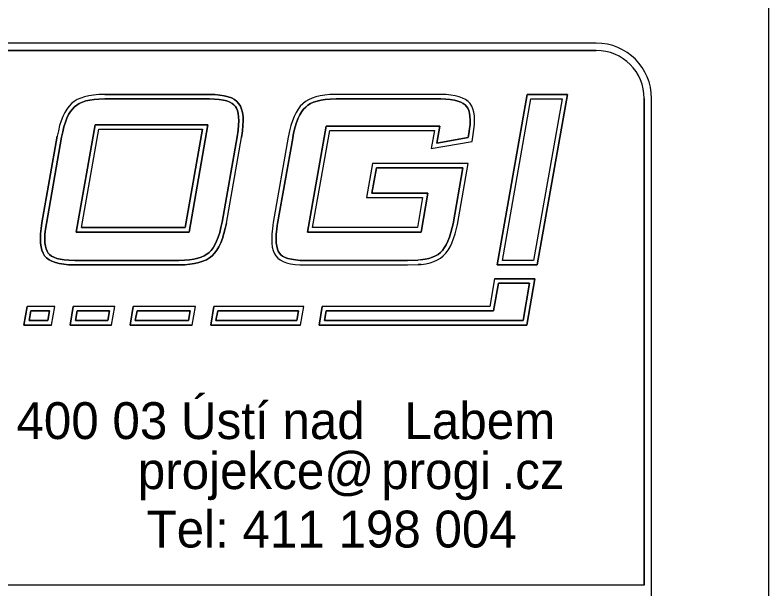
# Model space of a CAD drawing. Extents: x 249 to 564, y 49 to 194.
# Drawn here: x 544.18 to 563.59, y 70.96 to 85.75 of the extents above; entities that cross this region are included whole.
import ezdxf

# ---------------------------------------------------------------- set-up
doc = ezdxf.new("R2010")
doc.units = 0
doc.layers.add('000_rozpiska', color=7, linetype='Continuous')

msp = doc.modelspace()

# ---------------------------------------------------------------- linework, layer by layer
at = {"layer": '000_rozpiska'}
for p, q in [((563.594, 49.166), (563.594, 193.666)), ((559.147, 85.024), (472.697, 85.024)), ((559.147, 85.024), (472.697, 85.024)), ((559.147, 84.834), (532.072, 84.834)), ((552.155, 83.684), (552.037, 83.666)), ((552.288, 83.696), (552.155, 83.684)), ((552.447, 83.699), (552.288, 83.696)), ((555.144, 83.699), (552.447, 83.699)), ((555.278, 83.696), (555.144, 83.699)), ((555.402, 83.685), (555.278, 83.696)), ((555.515, 83.667), (555.402, 83.685)), ((556.592, 79.309), (557.366, 83.699)), ((557.366, 83.699), (558.402, 83.699)), ((558.402, 83.699), (557.629, 79.309)), ((545.832, 83.467), (545.911, 83.503)), ((545.911, 83.503), (546.001, 83.533)), ((546.001, 83.533), (546.102, 83.556)), ((546.102, 83.556), (546.214, 83.574)), ((546.214, 83.574), (546.338, 83.584)), ((546.338, 83.584), (546.493, 83.588)), ((546.493, 83.588), (549.183, 83.588)), ((549.183, 83.588), (549.316, 83.584)), ((549.316, 83.584), (549.436, 83.574)), ((549.436, 83.574), (549.543, 83.557)), ((549.543, 83.557), (549.633, 83.533)), ((549.633, 83.533), (549.706, 83.506)), ((549.706, 83.506), (549.77, 83.472)), ((551.656, 83.518), (551.587, 83.463)), ((551.735, 83.566), (551.656, 83.518)), ((551.826, 83.607), (551.735, 83.566)), ((551.867, 83.501), (551.788, 83.464)), ((551.926, 83.64), (551.826, 83.607)), ((551.957, 83.53), (551.867, 83.501)), ((552.037, 83.666), (551.926, 83.64)), ((552.059, 83.554), (551.957, 83.53)), ((552.169, 83.571), (552.059, 83.554)), ((552.294, 83.582), (552.169, 83.571)), ((552.449, 83.585), (552.294, 83.582)), ((555.142, 83.585), (552.449, 83.585)), ((555.272, 83.582), (555.142, 83.585)), ((555.388, 83.572), (555.272, 83.582)), ((555.492, 83.555), (555.388, 83.572)), ((555.586, 83.532), (555.492, 83.555)), ((555.62, 83.641), (555.515, 83.667)), ((555.66, 83.504), (555.586, 83.532)), ((555.706, 83.608), (555.62, 83.641)), ((555.722, 83.472), (555.66, 83.504)), ((555.782, 83.568), (555.706, 83.608)), ((555.847, 83.521), (555.782, 83.568)), ((555.899, 83.465), (555.847, 83.521)), ((556.728, 79.423), (557.461, 83.585)), ((557.461, 83.585), (558.267, 83.585)), ((558.267, 83.585), (557.533, 79.423)), ((560.382, 71.058), (560.382, 83.599)), ((560.572, 53.613), (560.572, 83.599)), ((560.572, 53.613), (560.572, 83.599)), ((545.605, 83.26), (545.655, 83.326)), ((545.655, 83.326), (545.707, 83.381)), ((545.707, 83.381), (545.766, 83.427)), ((545.766, 83.427), (545.832, 83.467)), ((549.77, 83.472), (549.815, 83.436)), ((549.815, 83.436), (549.853, 83.395)), ((549.853, 83.395), (549.882, 83.347)), ((549.882, 83.347), (549.905, 83.288)), ((551.468, 83.322), (551.415, 83.234)), ((551.524, 83.397), (551.468, 83.322)), ((551.587, 83.463), (551.524, 83.397)), ((551.611, 83.323), (551.562, 83.258)), ((551.664, 83.378), (551.611, 83.323)), ((551.721, 83.424), (551.664, 83.378)), ((551.788, 83.464), (551.721, 83.424)), ((555.77, 83.436), (555.722, 83.472)), ((555.808, 83.395), (555.77, 83.436)), ((555.837, 83.35), (555.808, 83.395)), ((555.862, 83.291), (555.837, 83.35)), ((555.881, 83.223), (555.862, 83.291)), ((555.938, 83.403), (555.899, 83.465)), ((555.97, 83.328), (555.938, 83.403)), ((555.993, 83.246), (555.97, 83.328)), ((545.514, 83.09), (545.558, 83.181)), ((545.558, 83.181), (545.605, 83.26)), ((549.905, 83.288), (549.924, 83.212)), ((549.924, 83.212), (549.935, 83.126)), ((549.935, 83.126), (549.939, 83.023)), ((551.366, 83.133), (551.322, 83.02)), ((551.415, 83.234), (551.366, 83.133)), ((551.515, 83.18), (551.47, 83.087)), ((551.562, 83.258), (551.515, 83.18)), ((555.893, 83.139), (555.881, 83.223)), ((555.899, 83.039), (555.893, 83.139)), ((556.007, 83.15), (555.993, 83.246)), ((556.013, 83.041), (556.007, 83.15)), ((545.437, 82.869), (545.474, 82.986)), ((545.474, 82.986), (545.514, 83.09)), ((545.751, 80.156), (546.238, 82.921)), ((546.238, 82.921), (549.146, 82.921)), ((548.659, 80.156), (549.146, 82.921)), ((549.935, 82.911), (549.922, 82.78)), ((549.939, 83.023), (549.935, 82.911)), ((551.285, 82.901), (551.249, 82.76)), ((551.322, 83.02), (551.285, 82.901)), ((551.43, 82.983), (551.395, 82.87)), ((551.47, 83.087), (551.43, 82.983)), ((555.884, 82.812), (555.896, 82.931)), ((555.896, 82.931), (555.899, 83.039)), ((555.998, 82.798), (556.01, 82.924)), ((556.01, 82.924), (556.013, 83.041)), ((545.376, 82.601), (545.405, 82.741)), ((545.405, 82.741), (545.437, 82.869)), ((545.887, 80.27), (546.334, 82.807)), ((546.334, 82.807), (549.01, 82.807)), ((548.563, 80.27), (549.01, 82.807)), ((549.922, 82.78), (549.897, 82.611)), ((551.249, 82.76), (551.232, 82.678)), ((551.36, 82.735), (551.344, 82.655)), ((551.395, 82.87), (551.36, 82.735)), ((551.707, 80.156), (552.188, 82.884)), ((551.843, 80.27), (552.283, 82.77)), ((552.188, 82.884), (555.116, 82.884)), ((552.283, 82.77), (554.98, 82.77)), ((554.98, 82.77), (554.898, 82.306)), ((555.116, 82.884), (555.039, 82.447)), ((555.866, 82.689), (555.884, 82.812)), ((555.979, 82.671), (555.998, 82.798)), ((544.872, 80.397), (545.265, 82.624)), ((544.985, 80.379), (545.376, 82.601)), ((549.897, 82.611), (549.509, 80.408)), ((549.621, 80.389), (550.009, 82.594)), ((551.216, 82.6), (550.828, 80.399)), ((551.328, 82.578), (550.941, 80.381)), ((551.232, 82.678), (551.216, 82.6)), ((551.344, 82.655), (551.328, 82.578)), ((555.039, 82.447), (555.849, 82.591)), ((555.849, 82.591), (555.866, 82.689)), ((555.947, 82.493), (555.979, 82.671)), ((554.898, 82.306), (555.947, 82.493)), ((553.388, 81.925), (553.233, 81.043)), ((553.484, 81.811), (553.369, 81.157)), ((555.847, 81.925), (553.388, 81.925)), ((555.712, 81.811), (553.484, 81.811)), ((555.458, 80.37), (555.712, 81.811)), ((555.569, 80.347), (555.847, 81.925)), ((553.369, 81.157), (554.812, 81.157)), ((554.812, 81.157), (554.635, 80.156)), ((553.233, 81.043), (554.676, 81.043)), ((554.676, 81.043), (554.54, 80.27)), ((544.962, 80.233), (544.985, 80.379)), ((549.509, 80.413), (549.479, 80.271)), ((550.828, 80.399), (550.82, 80.338)), ((550.941, 80.381), (550.933, 80.322)), ((544.949, 80.101), (544.962, 80.233)), ((545.887, 80.27), (548.563, 80.27)), ((549.479, 80.271), (549.449, 80.149)), ((550.806, 80.243), (550.792, 80.108)), ((550.82, 80.338), (550.806, 80.243)), ((550.92, 80.229), (550.906, 80.1)), ((550.933, 80.322), (550.92, 80.229)), ((554.54, 80.27), (551.843, 80.27)), ((555.402, 80.141), (555.435, 80.273)), ((555.435, 80.273), (555.458, 80.37)), ((555.512, 80.11), (555.546, 80.246)), ((555.546, 80.246), (555.569, 80.347)), ((544.944, 79.986), (544.949, 80.101)), ((545.751, 80.156), (548.659, 80.156)), ((549.41, 80.026), (549.37, 79.921)), ((549.449, 80.149), (549.41, 80.026)), ((550.792, 80.108), (550.788, 79.986)), ((550.906, 80.1), (550.902, 79.986)), ((554.635, 80.156), (551.707, 80.156)), ((555.325, 79.918), (555.366, 80.024)), ((555.366, 80.024), (555.402, 80.141)), ((555.473, 79.987), (555.512, 80.11)), ((544.948, 79.883), (544.944, 79.986)), ((544.96, 79.795), (544.948, 79.883)), ((544.978, 79.721), (544.96, 79.795)), ((549.325, 79.829), (549.279, 79.751)), ((549.37, 79.921), (549.325, 79.829)), ((550.788, 79.986), (550.791, 79.872)), ((550.791, 79.872), (550.804, 79.771)), ((550.902, 79.986), (550.905, 79.881)), ((550.905, 79.881), (550.916, 79.792)), ((555.234, 79.749), (555.28, 79.826)), ((555.28, 79.826), (555.325, 79.918)), ((555.381, 79.772), (555.43, 79.873)), ((555.43, 79.873), (555.473, 79.987)), ((545.002, 79.661), (544.978, 79.721)), ((545.031, 79.614), (545.002, 79.661)), ((545.066, 79.575), (545.031, 79.614)), ((549.176, 79.63), (549.119, 79.585)), ((549.229, 79.685), (549.176, 79.63)), ((549.279, 79.751), (549.229, 79.685)), ((550.804, 79.771), (550.826, 79.682)), ((550.826, 79.682), (550.855, 79.609)), ((550.855, 79.609), (550.895, 79.544)), ((550.916, 79.792), (550.935, 79.717)), ((550.935, 79.717), (550.958, 79.66)), ((550.958, 79.66), (550.987, 79.612)), ((550.987, 79.612), (551.023, 79.572)), ((555.074, 79.582), (555.132, 79.628)), ((555.132, 79.628), (555.185, 79.684)), ((555.185, 79.684), (555.234, 79.749)), ((555.208, 79.543), (555.273, 79.61)), ((555.273, 79.61), (555.329, 79.686)), ((555.329, 79.686), (555.381, 79.772)), ((545.114, 79.539), (545.066, 79.575)), ((545.174, 79.507), (545.114, 79.539)), ((545.25, 79.479), (545.174, 79.507)), ((545.341, 79.456), (545.25, 79.479)), ((545.446, 79.439), (545.341, 79.456)), ((545.564, 79.429), (545.446, 79.439)), ((545.721, 79.425), (545.564, 79.429)), ((548.393, 79.425), (545.721, 79.425)), ((548.546, 79.429), (548.393, 79.425)), ((548.669, 79.439), (548.546, 79.429)), ((548.782, 79.457), (548.669, 79.439)), ((548.883, 79.481), (548.782, 79.457)), ((548.973, 79.51), (548.883, 79.481)), ((549.053, 79.546), (548.973, 79.51)), ((549.119, 79.585), (549.053, 79.546)), ((550.895, 79.544), (550.946, 79.487)), ((550.946, 79.487), (551.009, 79.441)), ((551.009, 79.441), (551.086, 79.4)), ((551.023, 79.572), (551.07, 79.538)), ((551.07, 79.538), (551.133, 79.504)), ((551.133, 79.504), (551.207, 79.476)), ((551.207, 79.476), (551.297, 79.454)), ((551.297, 79.454), (551.403, 79.437)), ((551.403, 79.437), (551.522, 79.427)), ((551.522, 79.427), (551.675, 79.423)), ((551.675, 79.423), (554.283, 79.423)), ((554.283, 79.423), (554.557, 79.432)), ((554.624, 79.437), (554.557, 79.432)), ((554.624, 79.437), (554.737, 79.454)), ((554.737, 79.454), (554.836, 79.477)), ((554.836, 79.477), (554.926, 79.507)), ((554.926, 79.507), (555.004, 79.541)), ((554.967, 79.401), (555.056, 79.439)), ((555.004, 79.541), (555.074, 79.582)), ((555.056, 79.439), (555.138, 79.488)), ((555.138, 79.488), (555.208, 79.543)), ((557.533, 79.423), (556.728, 79.423)), ((551.086, 79.4), (551.173, 79.367)), ((551.173, 79.367), (551.275, 79.342)), ((551.275, 79.342), (551.389, 79.324)), ((551.389, 79.324), (551.516, 79.313)), ((551.516, 79.313), (551.674, 79.309)), ((551.674, 79.309), (554.284, 79.309)), ((554.284, 79.309), (554.564, 79.318)), ((554.637, 79.324), (554.564, 79.318)), ((554.637, 79.324), (554.758, 79.342)), ((554.758, 79.342), (554.867, 79.367)), ((554.867, 79.367), (554.967, 79.401)), ((557.629, 79.309), (556.592, 79.309)), ((556.529, 78.953), (556.403, 78.237)), ((556.625, 78.839), (556.499, 78.123)), ((556.529, 78.953), (557.566, 78.953)), ((556.625, 78.839), (557.43, 78.839)), ((557.43, 78.839), (557.261, 77.876)), ((557.566, 78.953), (557.356, 77.762)), ((544.408, 77.762), (544.492, 78.237)), ((545.204, 78.237), (544.492, 78.237)), ((544.544, 77.876), (544.587, 78.123)), ((545.068, 78.123), (544.587, 78.123)), ((545.025, 77.876), (545.068, 78.123)), ((545.121, 77.762), (545.204, 78.237)), ((545.596, 77.762), (545.679, 78.237)), ((546.748, 78.237), (545.679, 78.237)), ((545.731, 77.876), (545.775, 78.123)), ((546.612, 78.123), (545.775, 78.123)), ((546.569, 77.876), (546.612, 78.123)), ((546.664, 77.762), (546.748, 78.237)), ((547.139, 77.762), (547.223, 78.237)), ((548.826, 78.237), (547.223, 78.237)), ((547.275, 77.876), (547.319, 78.123)), ((548.69, 78.123), (547.319, 78.123)), ((548.647, 77.876), (548.69, 78.123)), ((548.742, 77.762), (548.826, 78.237)), ((549.217, 77.762), (549.301, 78.237)), ((551.617, 78.237), (549.301, 78.237)), ((549.353, 77.876), (549.397, 78.123)), ((551.481, 78.123), (549.397, 78.123)), ((551.437, 77.876), (551.481, 78.123)), ((551.533, 77.762), (551.617, 78.237)), ((552.008, 77.762), (552.092, 78.237)), ((556.403, 78.237), (552.092, 78.237)), ((552.144, 77.876), (552.187, 78.123)), ((556.499, 78.123), (552.187, 78.123)), ((545.025, 77.876), (544.544, 77.876)), ((546.569, 77.876), (545.731, 77.876)), ((548.647, 77.876), (547.275, 77.876)), ((551.437, 77.876), (549.353, 77.876)), ((557.261, 77.876), (552.144, 77.876)), ((545.121, 77.762), (544.408, 77.762)), ((546.664, 77.762), (545.596, 77.762)), ((548.742, 77.762), (547.139, 77.762)), ((551.533, 77.762), (549.217, 77.762)), ((557.356, 77.762), (552.008, 77.762)), ((560.382, 71.058), (532.072, 71.058))]:
    msp.add_line(p, q, dxfattribs=at)
for points in [[(532.072, 71.058), (532.072, 84.834), (559.147, 84.834)], [(549.566, 83.668), (549.45, 83.687), (549.323, 83.698), (549.186, 83.702), (546.491, 83.702), (546.332, 83.698), (546.201, 83.687), (546.08, 83.668), (545.97, 83.643), (545.869, 83.609), (545.779, 83.568), (545.701, 83.521), (545.63, 83.465), (545.568, 83.399), (545.511, 83.324), (545.457, 83.235), (545.41, 83.136), (545.366, 83.024), (545.327, 82.9), (545.294, 82.766), (545.265, 82.624), (544.872, 80.397), (544.849, 80.247), (544.836, 80.109), (544.83, 79.986), (544.834, 79.874), (544.847, 79.774), (544.869, 79.686), (544.899, 79.609), (544.939, 79.545), (544.989, 79.49), (545.053, 79.443), (545.127, 79.403), (545.216, 79.37), (545.317, 79.344), (545.432, 79.326), (545.558, 79.315), (545.718, 79.311), (548.395, 79.311), (548.552, 79.315), (548.683, 79.326), (548.803, 79.345), (548.914, 79.371), (549.014, 79.403), (549.105, 79.444), (549.184, 79.491), (549.253, 79.545), (549.316, 79.611), (549.373, 79.687), (549.426, 79.774), (549.474, 79.875), (549.518, 79.988), (549.559, 80.118), (549.59, 80.246), (549.621, 80.389), (550.009, 82.594), (550.035, 82.766), (550.048, 82.903), (550.053, 83.023), (550.049, 83.136), (550.036, 83.233), (550.014, 83.323), (549.984, 83.398), (549.944, 83.463), (549.894, 83.52), (549.832, 83.568), (549.754, 83.61), (549.667, 83.642), (549.566, 83.668)], [(546.491, 83.702), (546.332, 83.698), (546.201, 83.687), (546.08, 83.668), (545.97, 83.643), (545.869, 83.609), (545.779, 83.568), (545.701, 83.521), (545.63, 83.465), (545.568, 83.399), (545.511, 83.324), (545.457, 83.235), (545.41, 83.136), (545.366, 83.024), (545.327, 82.9), (545.294, 82.766), (545.265, 82.624)], [(546.491, 83.702), (549.186, 83.702), (549.323, 83.698), (549.45, 83.687), (549.566, 83.668), (549.667, 83.642), (549.754, 83.61), (549.832, 83.568), (549.894, 83.52), (549.944, 83.463), (549.984, 83.398), (550.014, 83.323), (550.036, 83.233), (550.049, 83.136), (550.053, 83.023), (550.048, 82.903), (550.035, 82.766), (550.009, 82.594)], [(555.62, 83.641), (555.515, 83.667), (555.402, 83.685), (555.278, 83.696), (555.144, 83.699), (552.447, 83.699), (552.288, 83.696), (552.155, 83.684), (552.037, 83.666), (551.926, 83.64), (551.826, 83.607), (551.735, 83.566), (551.656, 83.518), (551.587, 83.463), (551.524, 83.397), (551.468, 83.322), (551.415, 83.234), (551.366, 83.133), (551.322, 83.02), (551.285, 82.901), (551.249, 82.76), (551.232, 82.678), (551.216, 82.6), (550.828, 80.399), (550.82, 80.338), (550.806, 80.243), (550.792, 80.108), (550.788, 79.986), (550.791, 79.872), (550.804, 79.771), (550.826, 79.682), (550.855, 79.609), (550.895, 79.544), (550.946, 79.487), (551.009, 79.441), (551.086, 79.4), (551.173, 79.367), (551.275, 79.342), (551.389, 79.324), (551.516, 79.313), (551.674, 79.309), (554.284, 79.309), (554.564, 79.318), (554.637, 79.324), (554.758, 79.342), (554.867, 79.367), (554.967, 79.401), (555.056, 79.439), (555.138, 79.488), (555.208, 79.543), (555.273, 79.61), (555.329, 79.686), (555.381, 79.772), (555.43, 79.873), (555.473, 79.987), (555.512, 80.11), (555.546, 80.246), (555.569, 80.347), (555.847, 81.925), (553.388, 81.925), (553.233, 81.043), (554.676, 81.043), (554.54, 80.27), (551.843, 80.27), (552.283, 82.77), (554.98, 82.77), (554.898, 82.306), (555.947, 82.493), (555.979, 82.671), (555.998, 82.798), (556.01, 82.924), (556.013, 83.041), (556.007, 83.15), (555.993, 83.246), (555.97, 83.328), (555.938, 83.403), (555.899, 83.465), (555.847, 83.521), (555.782, 83.568), (555.706, 83.608), (555.62, 83.641)], [(558.402, 83.699), (557.366, 83.699), (556.592, 79.309), (557.629, 79.309), (558.402, 83.699)], [(560.382, 83.599), (560.382, 71.058), (532.072, 71.058)], [(549.939, 83.023), (549.935, 83.126), (549.924, 83.212), (549.905, 83.288), (549.882, 83.347), (549.853, 83.395), (549.815, 83.436), (549.77, 83.472), (549.706, 83.506), (549.633, 83.533), (549.543, 83.557), (549.436, 83.574), (549.316, 83.584), (549.183, 83.588), (546.493, 83.588), (546.338, 83.584), (546.214, 83.574), (546.102, 83.556), (546.001, 83.533), (545.911, 83.503), (545.832, 83.467), (545.766, 83.427), (545.707, 83.381), (545.655, 83.326), (545.605, 83.26), (545.558, 83.181), (545.514, 83.09), (545.474, 82.986), (545.437, 82.869), (545.405, 82.741), (545.376, 82.601), (544.985, 80.379), (544.962, 80.233), (544.949, 80.101), (544.944, 79.986), (544.948, 79.883), (544.96, 79.795), (544.978, 79.721), (545.002, 79.661), (545.031, 79.614), (545.066, 79.575), (545.114, 79.539), (545.174, 79.507), (545.25, 79.479), (545.341, 79.456), (545.446, 79.439), (545.564, 79.429), (545.721, 79.425), (548.393, 79.425), (548.546, 79.429), (548.669, 79.439), (548.782, 79.457), (548.883, 79.481), (548.973, 79.51), (549.053, 79.546), (549.119, 79.585), (549.176, 79.63), (549.229, 79.685), (549.279, 79.751), (549.325, 79.829), (549.37, 79.921), (549.41, 80.026), (549.449, 80.149), (549.479, 80.271), (549.509, 80.411), (549.897, 82.611), (549.922, 82.78), (549.935, 82.911), (549.939, 83.023)], [(549.183, 83.588), (549.316, 83.584), (549.436, 83.574), (549.543, 83.557), (549.633, 83.533), (549.706, 83.506), (549.77, 83.472), (549.815, 83.436), (549.853, 83.395), (549.882, 83.347), (549.905, 83.288), (549.924, 83.212), (549.935, 83.126), (549.939, 83.023), (549.935, 82.911), (549.922, 82.78), (549.897, 82.611), (549.509, 80.411), (549.479, 80.271), (549.449, 80.149), (549.41, 80.026), (549.37, 79.921), (549.325, 79.829), (549.279, 79.751), (549.229, 79.685), (549.176, 79.63), (549.119, 79.585), (549.053, 79.546), (548.973, 79.51), (548.883, 79.481), (548.782, 79.457), (548.669, 79.439), (548.546, 79.429), (548.393, 79.425), (545.721, 79.425), (545.564, 79.429), (545.446, 79.439), (545.341, 79.456), (545.25, 79.479), (545.174, 79.507), (545.114, 79.539), (545.066, 79.575), (545.031, 79.614), (545.002, 79.661), (544.978, 79.721), (544.96, 79.795), (544.948, 79.883), (544.944, 79.986), (544.949, 80.101), (544.962, 80.233), (544.985, 80.379), (545.376, 82.601), (545.405, 82.741), (545.437, 82.869), (545.474, 82.986), (545.514, 83.09), (545.558, 83.181), (545.605, 83.26), (545.655, 83.326), (545.707, 83.381), (545.766, 83.427), (545.832, 83.467), (545.911, 83.503), (546.001, 83.533), (546.102, 83.556), (546.214, 83.574), (546.338, 83.584), (546.493, 83.588), (549.183, 83.588)], [(555.142, 83.585), (555.272, 83.582), (555.388, 83.572), (555.492, 83.555), (555.586, 83.532), (555.66, 83.504), (555.722, 83.472), (555.77, 83.436), (555.808, 83.395), (555.837, 83.35), (555.862, 83.291), (555.881, 83.223), (555.893, 83.139), (555.899, 83.039), (555.896, 82.931), (555.884, 82.812), (555.866, 82.689), (555.849, 82.591), (555.039, 82.447), (555.116, 82.884), (552.188, 82.884), (551.707, 80.156), (554.635, 80.156), (554.812, 81.157), (553.369, 81.157), (553.484, 81.811), (555.712, 81.811), (555.458, 80.37), (555.435, 80.273), (555.402, 80.141), (555.366, 80.024), (555.325, 79.918), (555.28, 79.826), (555.234, 79.749), (555.185, 79.684), (555.132, 79.628), (555.074, 79.582), (555.004, 79.541), (554.926, 79.507), (554.836, 79.477), (554.737, 79.454), (554.624, 79.437), (554.557, 79.432), (554.283, 79.423), (551.675, 79.423), (551.522, 79.427), (551.403, 79.437), (551.297, 79.454), (551.207, 79.476), (551.133, 79.504), (551.07, 79.538), (551.023, 79.572), (550.987, 79.612), (550.958, 79.66), (550.935, 79.717), (550.916, 79.792), (550.905, 79.881), (550.902, 79.986), (550.906, 80.1), (550.92, 80.229), (550.933, 80.322), (550.941, 80.381), (551.328, 82.578), (551.344, 82.655), (551.36, 82.735), (551.395, 82.87), (551.43, 82.983), (551.47, 83.087), (551.515, 83.18), (551.562, 83.258), (551.611, 83.323), (551.664, 83.378), (551.721, 83.424), (551.788, 83.464), (551.867, 83.501), (551.957, 83.53), (552.059, 83.554), (552.169, 83.571), (552.294, 83.582), (552.449, 83.585), (555.142, 83.585)], [(558.267, 83.585), (557.533, 79.423), (556.728, 79.423), (557.461, 83.585), (558.267, 83.585)], [(549.146, 82.921), (548.659, 80.156), (545.751, 80.156), (546.238, 82.921), (549.146, 82.921)], [(549.146, 82.921), (546.238, 82.921), (545.751, 80.156), (548.659, 80.156), (549.146, 82.921)], [(549.01, 82.807), (548.563, 80.27), (545.887, 80.27), (546.334, 82.807), (549.01, 82.807)], [(545.718, 79.311), (545.558, 79.315), (545.432, 79.326), (545.317, 79.344), (545.216, 79.37), (545.127, 79.403), (545.053, 79.443), (544.989, 79.49), (544.939, 79.545), (544.899, 79.609), (544.869, 79.686), (544.847, 79.774), (544.834, 79.874), (544.83, 79.986), (544.836, 80.109), (544.849, 80.247), (544.872, 80.397)], [(549.621, 80.389), (549.59, 80.246), (549.559, 80.118), (549.518, 79.988), (549.474, 79.875), (549.426, 79.774), (549.373, 79.687), (549.316, 79.611), (549.253, 79.545), (549.184, 79.491), (549.105, 79.444), (549.014, 79.403), (548.914, 79.371), (548.803, 79.345), (548.683, 79.326), (548.552, 79.315), (548.395, 79.311), (545.718, 79.311)], [(557.566, 78.953), (556.529, 78.953), (556.403, 78.237), (552.092, 78.237), (552.008, 77.762), (557.356, 77.762), (557.566, 78.953)], [(557.43, 78.839), (557.261, 77.876), (552.144, 77.876), (552.187, 78.123), (556.499, 78.123), (556.625, 78.839), (557.43, 78.839)], [(557.43, 78.839), (556.625, 78.839), (556.499, 78.123), (552.187, 78.123), (552.144, 77.876), (557.261, 77.876), (557.43, 78.839)], [(545.204, 78.237), (544.492, 78.237), (544.408, 77.762), (545.121, 77.762), (545.204, 78.237)], [(545.068, 78.123), (545.025, 77.876), (544.544, 77.876), (544.587, 78.123), (545.068, 78.123)], [(545.068, 78.123), (544.587, 78.123), (544.544, 77.876), (545.025, 77.876), (545.068, 78.123)], [(546.748, 78.237), (545.679, 78.237), (545.596, 77.762), (546.664, 77.762), (546.748, 78.237)], [(546.612, 78.123), (546.569, 77.876), (545.731, 77.876), (545.775, 78.123), (546.612, 78.123)], [(546.612, 78.123), (545.775, 78.123), (545.731, 77.876), (546.569, 77.876), (546.612, 78.123)], [(548.826, 78.237), (547.223, 78.237), (547.139, 77.762), (548.742, 77.762), (548.826, 78.237)], [(548.69, 78.123), (548.647, 77.876), (547.275, 77.876), (547.319, 78.123), (548.69, 78.123)], [(548.69, 78.123), (547.319, 78.123), (547.275, 77.876), (548.647, 77.876), (548.69, 78.123)], [(551.617, 78.237), (549.301, 78.237), (549.217, 77.762), (551.533, 77.762), (551.617, 78.237)], [(551.481, 78.123), (551.437, 77.876), (549.353, 77.876), (549.397, 78.123), (551.481, 78.123)], [(551.481, 78.123), (549.397, 78.123), (549.353, 77.876), (551.437, 77.876), (551.481, 78.123)]]:
    msp.add_lwpolyline(points, dxfattribs=at)
for radius, start in [(1.425, 0), (1.425, 360), (1.235, 0), (1.235, 360)]:
    msp.add_arc((559.147, 83.599), radius, start, 90, dxfattribs=at)

# ---------------------------------------------------------------- texts
for s, p in [('400 03 Ústí nad', (544.214, 74.824)), ('Labem', (554.206, 74.824)), ('projekce@', (547.34, 73.535)), ('progi', (553.608, 73.535)), ('.cz', (556.707, 73.535)), ('Tel: 411 198 004', (547.565, 72.03))]:
    msp.add_text(s, height=0.95, dxfattribs=at).set_placement(p)

doc.saveas('drawing.dxf')
